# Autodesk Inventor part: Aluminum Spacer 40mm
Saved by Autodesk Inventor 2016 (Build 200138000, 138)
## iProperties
Created: 2015-11
Part Number: Aluminum Spacer 40mm
Material: Generic
Document SubType Name: Modeling
Designer: John
Density: 1 g/cm^3
Appearance: Default
Author: John
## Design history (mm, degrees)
feature "SOLID1"
body "Solid1"
